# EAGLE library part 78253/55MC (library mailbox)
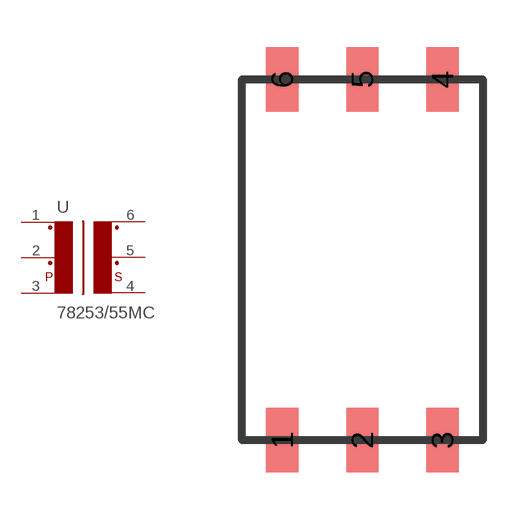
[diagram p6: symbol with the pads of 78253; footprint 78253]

Designator prefix -

## 78253/55MC  [78253]
1  1  pas
2  2  pas
3  3  pas
4  4  pas
5  5  pas
6  6  pas

## Footprint 78253 (pad centres in mm)
smd 1.016 x 2.032: 1 -1.27,-1.27; 2 1.27,-1.27; 3 3.81,-1.27; 4 3.81,10.16; 5 1.27,10.16; 6 -1.27,10.16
